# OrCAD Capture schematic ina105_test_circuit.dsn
size B; title: Precision Unity Gain Instrumentation Amplifier; rev: 1.0; company: Texas Instruments, Inc; note: Datasheet: SBOS145    EVM: N/A; note: 251 S William Circle; note: Tucson, AZ 85711
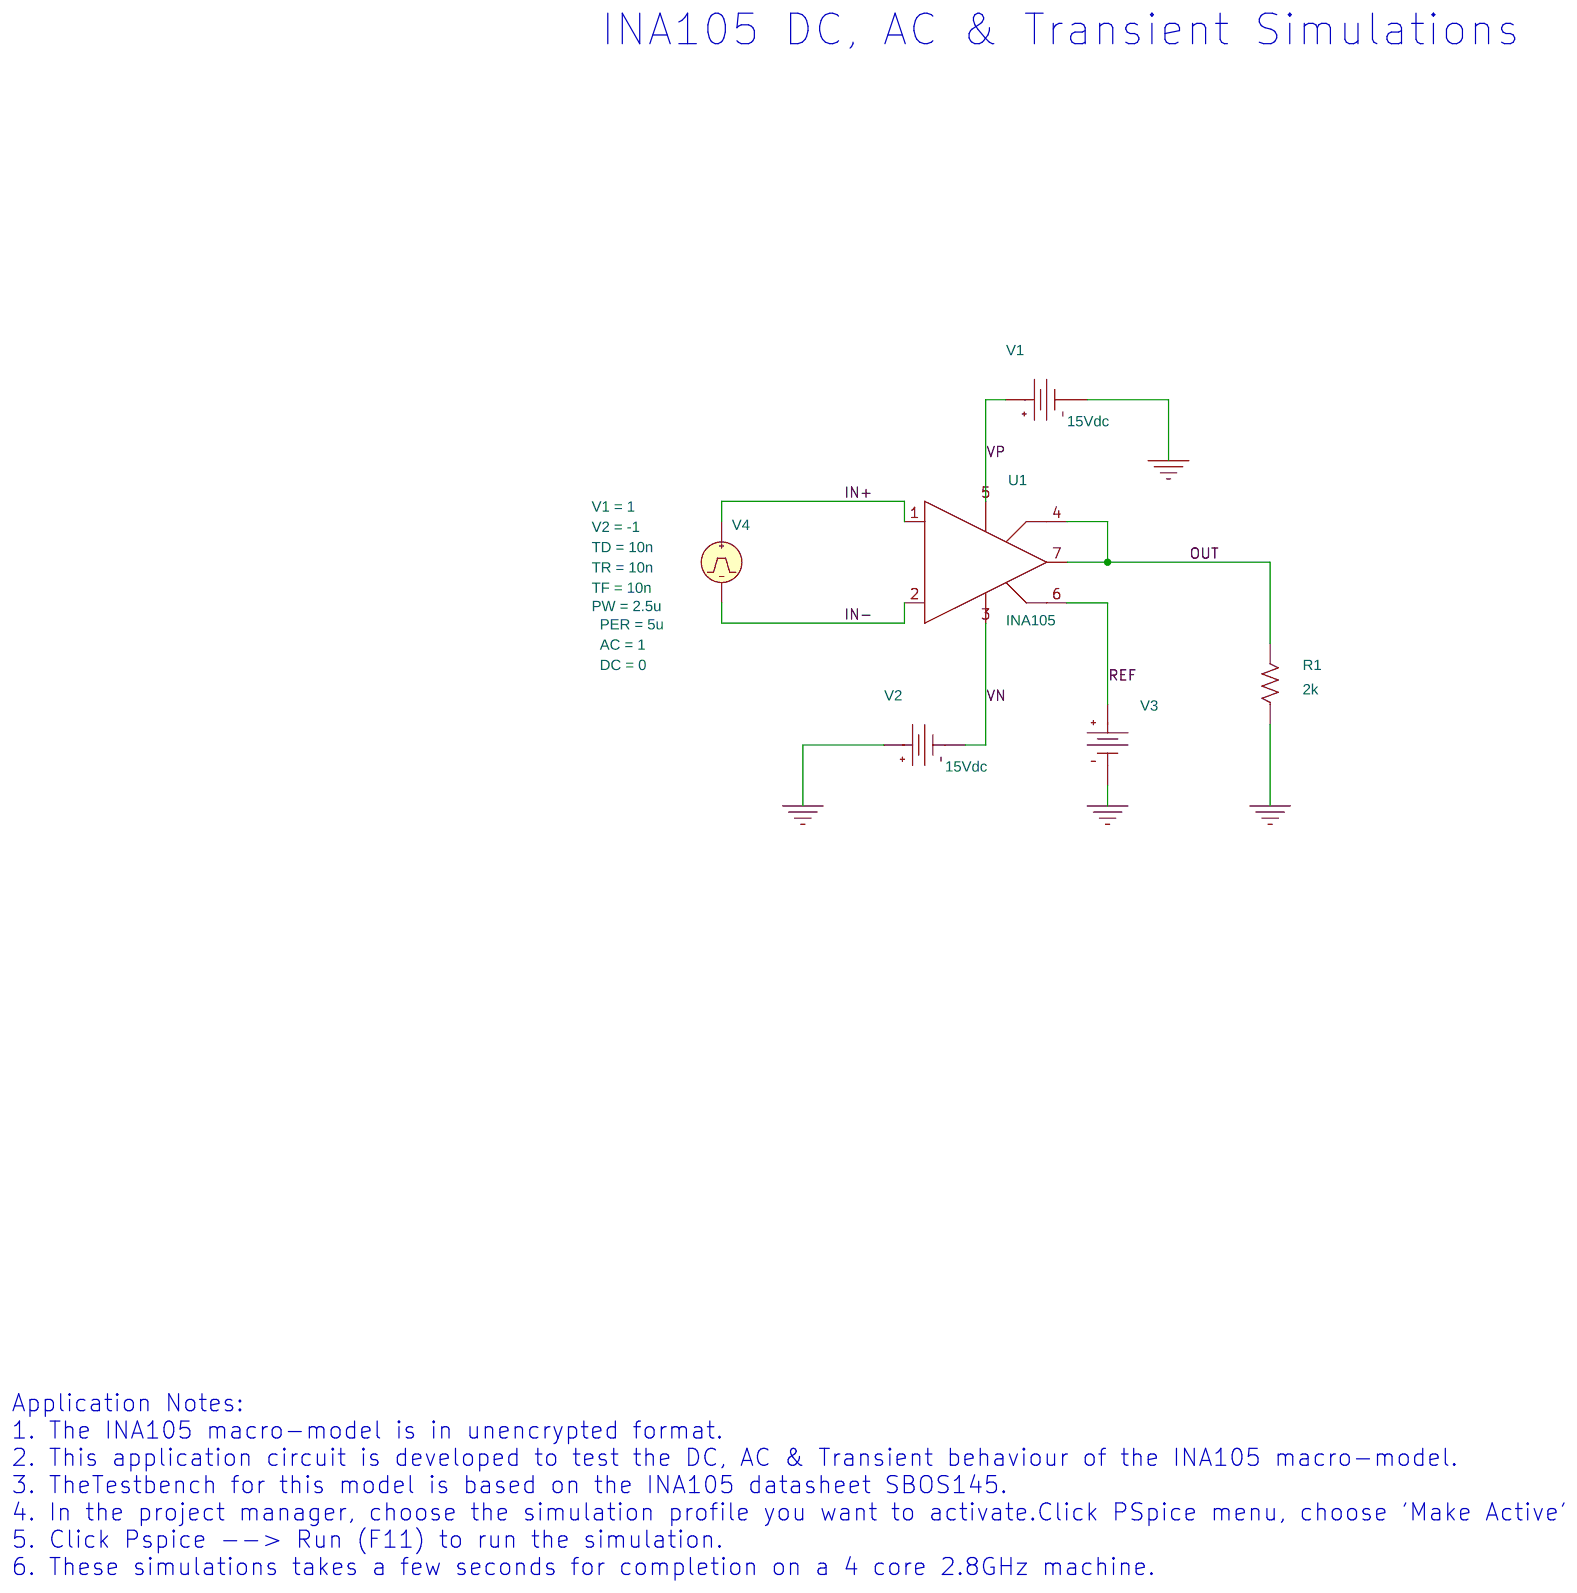
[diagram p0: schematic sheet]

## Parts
R1  2k  [AXRC05]
U1  INA105
V1  VDC
V2  VDC
V3  VDC
V4  VPULSE

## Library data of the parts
R1 = R
U1 = INA105
V1 V2 = VDC: DC: 15Vdc
V3 = VDC
V4 = VPULSE: AC: 1; AppProp: Pulse$Voltage$1$-1; DC: 0; PER: 5u; PW: 2.5u; TD: 10n; TF: 10n; TR: 10n; V1: 1; V2: -1

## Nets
0: R1.1 V1.1(-) V2.0(+) V3.1(-)
IN+: U1.1(+) V4.1(+)
IN-: U1.2(-) V4.2(-)
OUT: R1.2 U1.4(SENSE) U1.7(OUT)
REF: U1.6(REF) V3.0(+)
VN: U1.3(V-) V2.1(-)
VP: U1.5(V+) V1.0(+)

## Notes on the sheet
- INA105 DC, AC & Transient Simulations
- Application Notes:
  1. The INA105 macro-model is in unencrypted format.
  2. This application circuit is developed to test the DC, AC & Transient behaviour of the INA105 macro-model.
  3. TheTestbench for this model is based on the INA105 datasheet SBOS145.
  4. In the project manager, choose the simulation profile you want to activate.Click PSpice menu, choose 'Make Active'
  5. Click Pspice --> Run (F11) to run the simulation.
  6. These simulations takes a few seconds for completion on a 4 core 2.8GHz machine.
